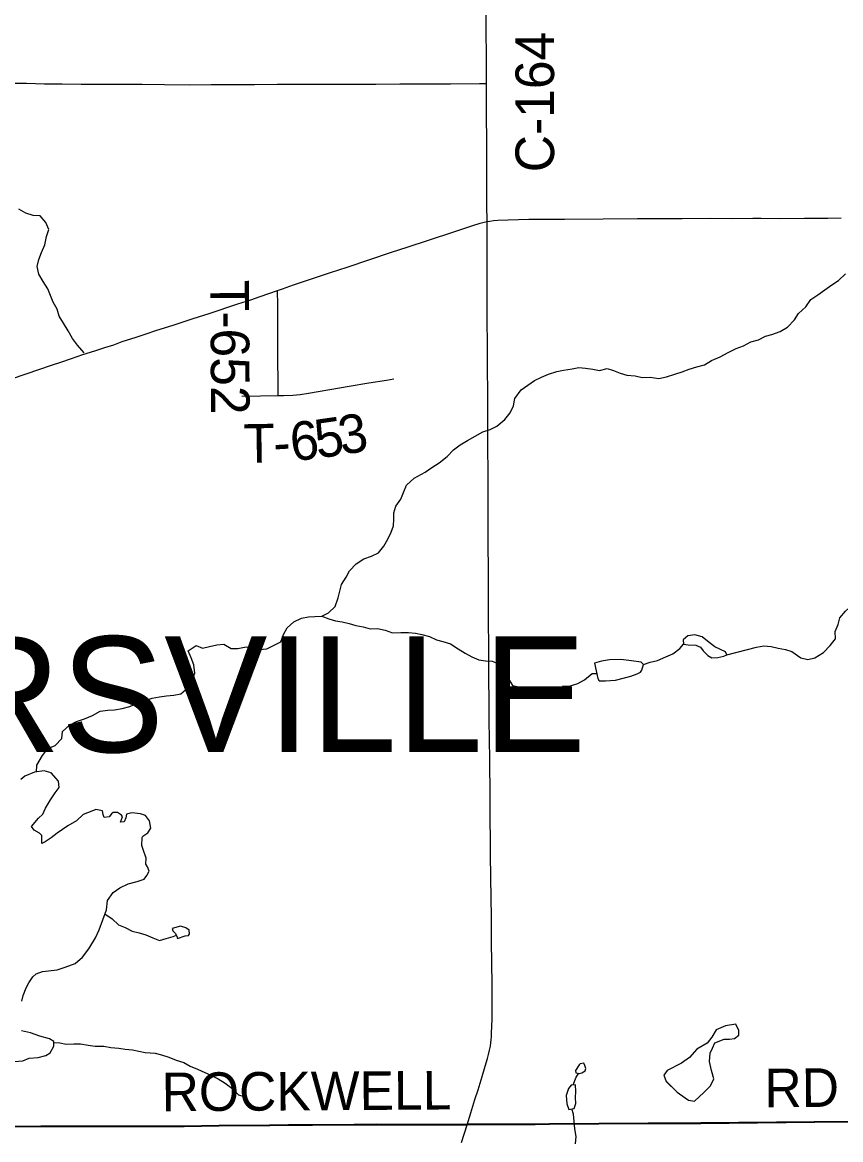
# Model space of a CAD drawing. Extents: x 0 to 34, y 0 to 22.
# Drawn here: x 14.455 to 15.659, y 12.652 to 14.297 of the extents above; entities that cross this region are included whole.
import ezdxf

# ---------------------------------------------------------------- set-up
doc = ezdxf.new("R2010")
doc.units = 0
for name, color, linetype in [('GM_X_Corporation', 7, 'Continuous'), ('GM_X_County_Road', 7, 'Continuous'), ('GM_X_County_Road_Text', 7, 'Continuous'), ('GM_X_Minor_Lake', 7, 'Continuous'), ('GM_X_Minor_River', 7, 'Continuous'), ('GM_X_Township_Road', 7, 'Continuous'), ('GM_X_Township_Road_Text', 7, 'Continuous'), ('GM_X_Township_Text', 7, 'Continuous')]:
    doc.layers.add(name, color=color, linetype=linetype)

msp = doc.modelspace()

# ---------------------------------------------------------------- linework, layer by layer
at = {"layer": 'GM_X_Corporation'}
for points in [[(15.6909, 12.6784), (15.6201, 12.6777), (15.453, 12.6762), (15.4275, 12.676), (15.3759, 12.6758), (15.2305, 12.6748), (15.2094, 12.6746), (15.1833, 12.6746), (15.161, 12.6745), (15.1356, 12.6745), (15.109, 12.6743), (15.0726, 12.6741), (15.0335, 12.674), (15.0186, 12.6741), (14.9758, 12.6742), (14.943, 12.674), (14.8815, 12.6737), (14.8467, 12.6734), (14.8188, 12.6732), (14.7442, 12.6724), (14.6926, 12.6717), (14.664, 12.6716), (14.628, 12.6715), (14.6025, 12.6716), (14.5529, 12.6716), (14.54, 12.6716), (14.5214, 12.6716), (14.4819, 12.6715), (14.4274, 12.671)], [(14.4274, 12.671), (14.4819, 12.6715), (14.5214, 12.6716), (14.54, 12.6716), (14.5529, 12.6716), (14.6025, 12.6716), (14.628, 12.6715), (14.664, 12.6716), (14.6926, 12.6717), (14.7442, 12.6724), (14.8188, 12.6732), (14.8467, 12.6734), (14.8815, 12.6737), (14.943, 12.674), (14.9758, 12.6742), (15.0186, 12.6741), (15.0335, 12.674), (15.0726, 12.6741), (15.109, 12.6743), (15.1356, 12.6745), (15.161, 12.6745), (15.1833, 12.6746), (15.2094, 12.6746), (15.2305, 12.6748), (15.3759, 12.6758), (15.4275, 12.676), (15.453, 12.6762), (15.6201, 12.6777), (15.6909, 12.6784)]]:
    msp.add_lwpolyline(points, dxfattribs=at)
at = {"layer": 'GM_X_County_Road'}
for points in [[(15.1377, 14.2067), (15.1376, 14.2438), (15.1374, 14.2874), (15.1373, 14.3074)], [(15.1386, 14.0035), (15.1385, 14.0278), (15.1382, 14.0758), (15.1381, 14.1118), (15.1378, 14.1694), (15.1377, 14.1931), (15.1377, 14.2067)], [(14.8302, 13.9017), (14.8379, 13.9046), (14.8538, 13.9101), (14.8849, 13.9207), (14.9082, 13.9283), (14.9327, 13.9364), (14.966, 13.9475), (14.9967, 13.9578), (15.0228, 13.9664), (15.051, 13.9755), (15.0912, 13.9887), (15.1178, 13.9977), (15.1287, 14.0011), (15.1346, 14.0026), (15.1386, 14.0035)], [(15.1092, 12.6737), (15.1147, 12.6909), (15.1209, 12.7106), (15.1254, 12.7252), (15.1314, 12.7446), (15.1359, 12.7598), (15.1391, 12.771), (15.1407, 12.7771), (15.1422, 12.7832), (15.1435, 12.7894), (15.1441, 12.7941), (15.1447, 12.7987), (15.1452, 12.8033), (15.1454, 12.8071), (15.1459, 12.8204), (15.146, 12.8276), (15.146, 12.8364), (15.146, 12.8518), (15.146, 12.88), (15.1452, 12.9432), (15.145, 12.9815), (15.1447, 13.0056), (15.1442, 13.0394), (15.1439, 13.0693), (15.1437, 13.08), (15.1436, 13.0926), (15.1433, 13.1233), (15.1431, 13.1543), (15.1426, 13.2136), (15.1423, 13.2386), (15.142, 13.2717), (15.1417, 13.3048), (15.1415, 13.323), (15.1414, 13.3568), (15.1412, 13.3812), (15.1409, 13.4115), (15.1407, 13.4449), (15.1407, 13.472), (15.1405, 13.547), (15.1405, 13.5743), (15.1403, 13.6288), (15.14, 13.6767), (15.1398, 13.7092), (15.1396, 13.7446), (15.1394, 13.7943), (15.1392, 13.8221), (15.139, 13.8581), (15.1389, 13.8814), (15.1388, 13.9037), (15.1387, 13.9347), (15.1386, 13.9787), (15.1386, 14.0035)], [(15.1386, 14.0035), (15.1428, 14.0042), (15.1482, 14.005), (15.1546, 14.0055), (15.2002, 14.0069), (15.2288, 14.0071), (15.2524, 14.0072), (15.3096, 14.0074), (15.3599, 14.0079), (15.386, 14.008), (15.4258, 14.008), (15.4681, 14.0082), (15.4991, 14.0081), (15.5295, 14.0083), (15.5419, 14.0082), (15.5698, 14.0081), (15.6059, 14.0084), (15.6401, 14.0085), (15.6599, 14.0087)], [(14.4197, 13.7655), (14.4792, 13.7854), (14.498, 13.792), (14.5115, 13.7966), (14.5274, 13.802), (14.5438, 13.8075), (14.5616, 13.8131), (14.5764, 13.8179), (14.5894, 13.8221), (14.6016, 13.8266), (14.6223, 13.8334), (14.637, 13.8383), (14.6512, 13.8428), (14.6785, 13.8513), (14.7062, 13.8605), (14.7298, 13.8683), (14.7722, 13.8822), (14.7911, 13.8884), (14.8046, 13.8932), (14.8302, 13.9017)], [(14.4276, 12.6705), (14.4821, 12.671), (14.5216, 12.6711), (14.5402, 12.671), (14.5531, 12.671), (14.6027, 12.671), (14.6282, 12.671), (14.6643, 12.6711), (14.6928, 12.6712), (14.7444, 12.6718), (14.819, 12.6727), (14.8469, 12.6729), (14.8817, 12.6732), (14.9432, 12.6735), (14.976, 12.6737), (15.0188, 12.6735), (15.0337, 12.6735), (15.0728, 12.6735), (15.1092, 12.6737)], [(15.1012, 12.6474), (15.1092, 12.6737)], [(15.1092, 12.6737), (15.1358, 12.6739), (15.1612, 12.6739), (15.1835, 12.6741), (15.2096, 12.6741), (15.2307, 12.6742), (15.3761, 12.6753), (15.4277, 12.6755), (15.4532, 12.6756), (15.6203, 12.6772), (15.6911, 12.6779), (15.7496, 12.6784), (15.9075, 12.6789)]]:
    msp.add_lwpolyline(points, dxfattribs=at)
at = {"layer": 'GM_X_Minor_Lake'}
for p, q in [((15.4456, 13.3797), (15.4525, 13.3768)), ((15.2967, 13.3532), (15.3018, 13.3305)), ((14.6833, 12.9476), (14.6946, 12.9515)), ((15.2741, 12.7617), (15.2688, 12.7534)), ((15.4022, 12.7373), (15.4182, 12.7215)), ((15.4182, 12.7215), (15.403, 12.7369)), ((15.2551, 12.7168), (15.2558, 12.7044))]:
    msp.add_line(p, q, dxfattribs=at)
for points in [[(15.4525, 13.3768), (15.4567, 13.3715), (15.4635, 13.3643), (15.4696, 13.3613), (15.4783, 13.3618), (15.487, 13.3634), (15.4915, 13.3653), (15.4896, 13.3698), (15.474, 13.3773), (15.4653, 13.3837), (15.455, 13.3919), (15.4444, 13.3949), (15.4342, 13.3933), (15.4274, 13.3876), (15.4275, 13.3811), (15.4347, 13.3804), (15.4456, 13.3797)], [(15.3018, 13.3305), (15.3034, 13.3274), (15.306, 13.3271), (15.3128, 13.3271), (15.3276, 13.328), (15.3408, 13.3315), (15.3502, 13.3343), (15.3597, 13.3374), (15.3646, 13.3401), (15.3664, 13.3427), (15.3687, 13.3511), (15.3652, 13.3545), (15.3512, 13.3566), (15.3357, 13.3584), (15.319, 13.3579), (15.3069, 13.3563), (15.2967, 13.3532)], [(14.4543, 12.8556), (14.4561, 12.864), (14.4606, 12.8754), (14.4647, 12.8826), (14.4703, 12.8914), (14.4752, 12.8956), (14.4846, 12.8991), (14.5062, 12.9019), (14.5179, 12.9058), (14.5326, 12.9112), (14.5435, 12.9204), (14.5525, 12.9326), (14.5626, 12.9486), (14.5678, 12.9604), (14.5733, 12.9752), (14.5785, 12.9901), (14.5803, 13.0037), (14.5886, 13.0155), (14.5983, 13.0224), (14.6108, 13.0282), (14.624, 13.0317), (14.6342, 13.0352), (14.6379, 13.0406), (14.6413, 13.047), (14.6393, 13.0535), (14.6367, 13.0573), (14.637, 13.066), (14.6327, 13.0788), (14.6308, 13.0849), (14.6311, 13.0963), (14.6322, 13.0986), (14.6397, 13.1035), (14.6438, 13.1104), (14.6419, 13.121), (14.6361, 13.1289), (14.6289, 13.1315), (14.616, 13.1329), (14.6081, 13.131), (14.6074, 13.1257), (14.6048, 13.1196), (14.5995, 13.1192), (14.6021, 13.1272), (14.6009, 13.1294), (14.5948, 13.1335), (14.5884, 13.1331), (14.5861, 13.1312), (14.5828, 13.127), (14.5752, 13.1262), (14.5737, 13.1303), (14.5729, 13.136), (14.563, 13.1379), (14.557, 13.1352), (14.5445, 13.1305), (14.5344, 13.1209), (14.5216, 13.1136), (14.5061, 13.1029), (14.4971, 13.096), (14.4884, 13.0903), (14.4835, 13.0879), (14.4838, 13.0993), (14.48, 13.1027), (14.4724, 13.1072), (14.4686, 13.1129), (14.4787, 13.1251), (14.4851, 13.1308), (14.4892, 13.1396), (14.4963, 13.1518), (14.5034, 13.1621), (14.509, 13.1701), (14.5082, 13.1795), (14.4971, 13.1916), (14.4869, 13.1945), (14.4729, 13.1925), (14.4585, 13.1867), (14.4529, 13.1821)], [(14.6946, 12.9515), (14.6992, 12.9523), (14.7007, 12.9546), (14.7006, 12.9603), (14.6953, 12.9633), (14.6877, 12.9662), (14.6753, 12.9623), (14.6764, 12.9589), (14.6798, 12.9556), (14.6822, 12.9514), (14.6833, 12.9476)], [(15.5048, 12.8219), (15.4893, 12.8191), (15.4758, 12.8133), (15.4694, 12.8023), (15.4623, 12.7939), (15.4472, 12.7847), (15.4367, 12.7725), (15.4247, 12.7644), (15.4039, 12.7536), (15.3987, 12.7468), (15.4022, 12.7373)], [(15.4182, 12.7215), (15.4216, 12.7189), (15.4349, 12.7099), (15.444, 12.7084), (15.4576, 12.721), (15.4673, 12.731), (15.4725, 12.7413), (15.469, 12.7534), (15.4659, 12.7666), (15.4669, 12.7788), (15.4703, 12.7864), (15.474, 12.794), (15.4876, 12.7998), (15.4955, 12.7998), (15.5027, 12.8007), (15.5091, 12.8056), (15.5091, 12.8125), (15.5048, 12.8219), (15.4893, 12.8191), (15.4758, 12.8133), (15.4694, 12.8023), (15.4623, 12.7939), (15.4472, 12.7847), (15.4367, 12.7725), (15.4247, 12.7644), (15.4039, 12.7536), (15.3987, 12.7468), (15.4022, 12.7373)], [(15.4182, 12.7215), (15.4216, 12.7189), (15.4349, 12.7099), (15.444, 12.7084), (15.4576, 12.721), (15.4673, 12.731), (15.4725, 12.7413), (15.469, 12.7534), (15.4659, 12.7666), (15.4669, 12.7788), (15.4703, 12.7864), (15.474, 12.794), (15.4876, 12.7998), (15.4955, 12.7998), (15.5027, 12.8007), (15.5091, 12.8056), (15.5091, 12.8125), (15.5048, 12.8219)], [(14.4429, 12.7668), (14.4554, 12.7676), (14.4648, 12.7715), (14.478, 12.7724), (14.4894, 12.7755), (14.4958, 12.7793), (14.501, 12.7892), (14.5013, 12.796), (14.4948, 12.8002), (14.4804, 12.8039), (14.4668, 12.8091), (14.4539, 12.812)], [(15.2688, 12.7534), (15.2692, 12.7499), (15.2745, 12.7492), (15.2783, 12.75), (15.2832, 12.7531), (15.2839, 12.7565), (15.2824, 12.761), (15.2812, 12.7641), (15.2756, 12.7633), (15.2741, 12.7617)], [(15.2558, 12.7044), (15.259, 12.696), (15.267, 12.6976), (15.2692, 12.7048), (15.2687, 12.7139), (15.2691, 12.7226), (15.269, 12.7325), (15.2622, 12.7321), (15.2584, 12.7271), (15.2551, 12.7168)]]:
    msp.add_lwpolyline(points, dxfattribs=at)
at = {"layer": 'GM_X_Minor_River'}
for points in [[(14.5457, 13.8102), (14.5362, 13.8215), (14.5285, 13.8313), (14.5224, 13.8423), (14.5155, 13.8536), (14.5093, 13.8642), (14.5062, 13.8744), (14.5001, 13.8846), (14.4962, 13.8944), (14.4924, 13.9046), (14.4855, 13.9152), (14.479, 13.9261), (14.4766, 13.9371), (14.4792, 13.9478), (14.4829, 13.958), (14.4881, 13.9694), (14.4906, 13.9812), (14.494, 13.9919), (14.4897, 14.0021), (14.4809, 14.0119), (14.4707, 14.0122), (14.4601, 14.0159), (14.4498, 14.0215)], [(15.3669, 13.7736), (15.3786, 13.7744), (15.3915, 13.7726), (15.4025, 13.775), (15.4149, 13.7789), (15.4259, 13.782), (15.4361, 13.7863), (15.4474, 13.7894), (15.4584, 13.7925), (15.4689, 13.7987), (15.4814, 13.8044), (15.4934, 13.8106), (15.5051, 13.8164), (15.516, 13.8206), (15.527, 13.8264), (15.5379, 13.8295), (15.5481, 13.8345), (15.5579, 13.8373), (15.57, 13.8415), (15.5809, 13.8481), (15.5911, 13.8588), (15.5967, 13.8683), (15.6076, 13.8778), (15.6151, 13.8885), (15.6252, 13.8954), (15.6358, 13.9031), (15.6459, 13.9104), (15.6557, 13.9165), (15.6659, 13.9265)], [(14.4755, 13.1929), (14.4762, 13.2028), (14.4844, 13.2173), (14.4923, 13.2276), (14.5032, 13.2322), (14.513, 13.2422), (14.514, 13.2528), (14.5242, 13.262), (14.5344, 13.2673), (14.5465, 13.2712), (14.5581, 13.2763), (14.5695, 13.2824), (14.5808, 13.284), (14.5906, 13.2845), (14.6016, 13.2864), (14.6129, 13.2892), (14.6231, 13.2938), (14.6458, 13.3016), (14.6567, 13.3036), (14.6669, 13.3051), (14.6779, 13.306), (14.6881, 13.308), (14.6982, 13.3168), (14.7046, 13.3286), (14.7087, 13.3385), (14.7074, 13.3506), (14.7032, 13.3612), (14.699, 13.3714), (14.7106, 13.3791), (14.7201, 13.3753), (14.7303, 13.3777), (14.7409, 13.3804), (14.7515, 13.3813), (14.7621, 13.3749), (14.772, 13.375), (14.7841, 13.3773), (14.7943, 13.3751), (14.8038, 13.3733), (14.8148, 13.3742), (14.8351, 13.3846), (14.8392, 13.3956), (14.8444, 13.4051), (14.8546, 13.4143), (14.8655, 13.4193), (14.8757, 13.4213), (14.8855, 13.4221), (14.8958, 13.4222), (14.9056, 13.4272), (14.9153, 13.4368), (14.9194, 13.4493), (14.9245, 13.4691), (14.9313, 13.4797), (14.9361, 13.4893), (14.9463, 13.4996), (14.9572, 13.5069), (14.9685, 13.5107), (14.9787, 13.5158), (14.9869, 13.5257), (14.9925, 13.536), (14.9978, 13.5459), (15.0011, 13.5554), (15.0014, 13.5652), (15.0017, 13.5747), (15.0046, 13.5846), (15.0118, 13.5949), (15.0155, 13.6044), (15.0199, 13.6151), (15.0316, 13.6258), (15.0474, 13.6346), (15.0572, 13.6411), (15.0681, 13.6481), (15.0798, 13.6576), (15.0892, 13.6672), (15.0989, 13.6748), (15.1099, 13.681), (15.1212, 13.6875), (15.1325, 13.6937), (15.1431, 13.6972), (15.1532, 13.7022), (15.1649, 13.7118), (15.1728, 13.7217), (15.1776, 13.7323), (15.1794, 13.743), (15.1888, 13.7556), (15.1986, 13.7625), (15.2087, 13.7694), (15.2189, 13.7744), (15.2291, 13.7786), (15.2412, 13.7825), (15.251, 13.7845), (15.2639, 13.7868), (15.2737, 13.7888), (15.2835, 13.7878), (15.2941, 13.7863), (15.304, 13.7841), (15.3153, 13.7869), (15.3248, 13.7843), (15.3343, 13.7802), (15.3442, 13.7772), (15.3567, 13.7762), (15.3669, 13.7736)], [(15.4915, 13.3653), (15.535, 13.377), (15.5459, 13.3786), (15.5569, 13.3776), (15.5672, 13.3754), (15.5778, 13.3735), (15.5873, 13.3702), (15.6002, 13.3612), (15.6108, 13.3586), (15.621, 13.361), (15.6335, 13.369), (15.6436, 13.3793), (15.6511, 13.3889), (15.651, 13.3999), (15.6551, 13.4102), (15.6577, 13.42), (15.6659, 13.4296), (15.6757, 13.4384), (15.6866, 13.4438), (15.6929, 13.4438)], [(14.8958, 13.4222), (14.906, 13.4185), (14.9155, 13.4155), (14.9253, 13.4141), (14.9356, 13.4115), (14.9458, 13.4085), (14.9564, 13.4067), (14.9667, 13.4038), (14.9773, 13.4042), (14.9886, 13.4017), (14.9996, 13.398), (15.0118, 13.3984), (15.0231, 13.3985), (15.0333, 13.3975), (15.0428, 13.3956), (15.0542, 13.3927), (15.0641, 13.3874), (15.0736, 13.3849), (15.0849, 13.3815), (15.096, 13.3744), (15.1066, 13.3677), (15.1161, 13.3624), (15.1264, 13.3583), (15.1366, 13.3565), (15.1464, 13.3562), (15.1559, 13.3521), (15.1655, 13.3419), (15.1701, 13.3302), (15.1759, 13.3204), (15.1853, 13.3182), (15.1959, 13.3171), (15.2058, 13.3153), (15.213, 13.3158)], [(15.3687, 13.3511), (15.3785, 13.3546), (15.3894, 13.3573), (15.4019, 13.3627), (15.4121, 13.367), (15.4222, 13.3746), (15.4275, 13.3811)], [(15.2497, 13.3198), (15.2595, 13.3195), (15.272, 13.3234), (15.2818, 13.3288), (15.2931, 13.338), (15.3001, 13.338)], [(14.5764, 12.984), (14.587, 12.9768), (14.5965, 12.9678), (14.606, 12.9641), (14.6166, 12.9585), (14.6269, 12.9563), (14.6367, 12.9533), (14.647, 12.9489), (14.6568, 12.9451), (14.6667, 12.9479), (14.6769, 12.9506), (14.6815, 12.9526)], [(14.5012, 12.7945), (14.51, 12.7942), (14.5195, 12.7924), (14.5305, 12.7929), (14.5407, 12.7926), (14.5517, 12.7907), (14.5623, 12.7893), (14.5748, 12.7894), (14.585, 12.7872), (14.5968, 12.7865), (14.6062, 12.7847), (14.6172, 12.7837), (14.6358, 12.78), (14.6502, 12.779), (14.6597, 12.7764), (14.6703, 12.7731), (14.6813, 12.7686), (14.6923, 12.7653), (14.7018, 12.7597), (14.7128, 12.7556), (14.7333, 12.7459), (14.7432, 12.741), (14.7535, 12.735), (14.763, 12.7275), (14.7729, 12.7177), (14.7794, 12.7155)], [(15.2652, 12.7323), (15.27, 12.7436), (15.2738, 12.7493)], [(15.2689, 12.6457), (15.2696, 12.6563), (15.268, 12.6676), (15.2668, 12.6786), (15.2659, 12.6892), (15.2633, 12.6969)]]:
    msp.add_lwpolyline(points, dxfattribs=at)
at = {"layer": 'GM_X_Township_Road'}
for points in [[(14.4338, 14.2074), (14.4549, 14.2073), (14.4612, 14.2071), (14.4873, 14.2064), (14.5133, 14.206), (14.5413, 14.2056), (14.5677, 14.2055), (14.6008, 14.2055), (14.6312, 14.2055), (14.6642, 14.2052), (14.7015, 14.2048), (14.7325, 14.2051), (14.7637, 14.2051), (14.7966, 14.205), (14.8298, 14.2055), (14.8631, 14.2057), (14.9079, 14.2055), (14.9438, 14.2058), (14.9748, 14.2055), (15.0104, 14.2061), (15.0421, 14.2061), (15.0552, 14.206), (15.0663, 14.206), (15.0849, 14.206), (15.1274, 14.2065), (15.1377, 14.2067)], [(14.8313, 13.7473), (14.8312, 13.7549), (14.8311, 13.7599), (14.8309, 13.8077), (14.8307, 13.8456), (14.8306, 13.8804), (14.8302, 13.9017)], [(14.8313, 13.7473), (14.8394, 13.7474), (14.8531, 13.7478), (14.8636, 13.7488), (14.8759, 13.7506), (14.936, 13.7609), (14.9648, 13.7659), (14.9906, 13.77), (15.0016, 13.7718)], [(14.7779, 13.7463), (14.8052, 13.7469), (14.8313, 13.7473)]]:
    msp.add_lwpolyline(points, dxfattribs=at)

# ---------------------------------------------------------------- texts
at = {"layer": 'GM_X_County_Road_Text'}
for s, rotation, p in [('C-164', 90, (15.2373, 14.076)), ('ROCKWELL', 0.3709, (14.66, 12.6934)), ('RD', 0.4827, (15.547, 12.6992))]:
    msp.add_text(s, height=0.05682, rotation=rotation, dxfattribs=at).set_placement(p)
at = {"layer": 'GM_X_Township_Road_Text'}
for s, height, rotation, p in [('T-652', 0.05682, 270.2823, (14.7316, 13.9176)), ('3', 0.0568, 9.228, (14.9247, 13.6597)), ('T', 0.0568, 0.9858, (14.7806, 13.6482)), ('6', 0.0568, 5.8438, (14.8516, 13.6506)), ('5', 0.0568, 8.2952, (14.8891, 13.6545)), ('-', 0.0568, 3.3098, (14.8256, 13.6491))]:
    msp.add_text(s, height=height, rotation=rotation, dxfattribs=at).set_placement(p)
at = {"layer": 'GM_X_Township_Text'}
msp.add_text('SHALERSVILLE', height=0.170455, rotation=0, dxfattribs=at).set_placement((13.5994, 13.2222))

doc.saveas('drawing.dxf')
